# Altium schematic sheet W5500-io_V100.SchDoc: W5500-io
size A4; DrawnBy: Scott; Revision: V100; SheetNumber: 1; SheetTotal: 1; Team: Edge
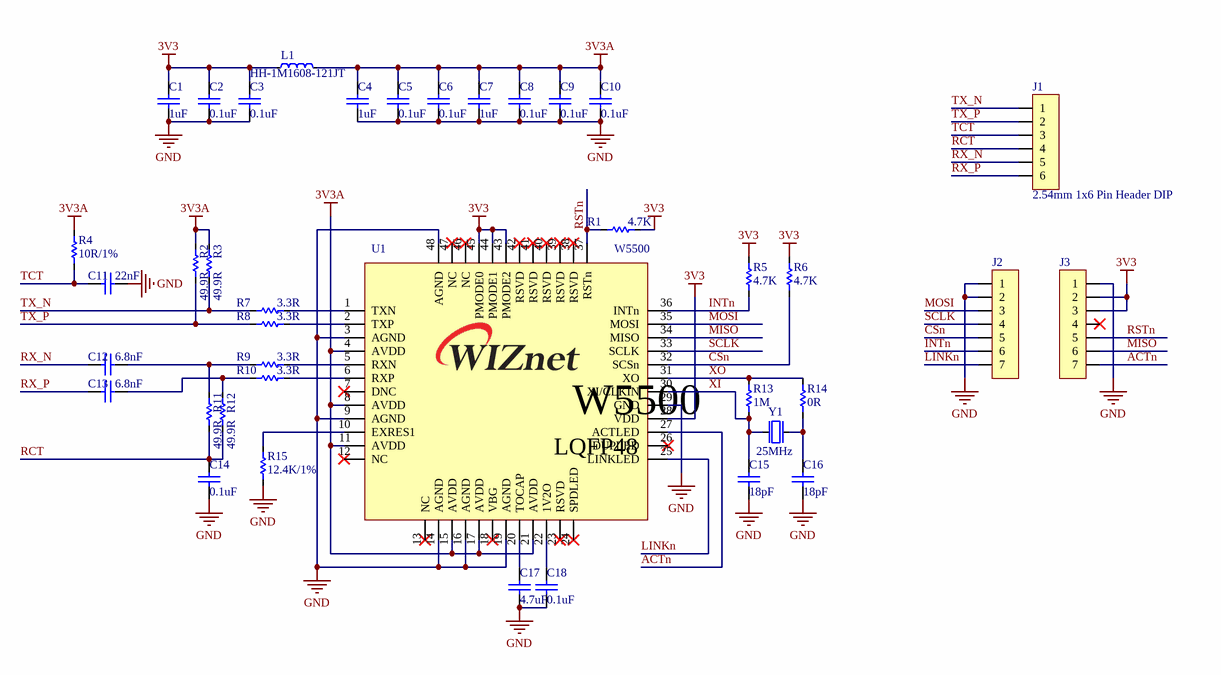
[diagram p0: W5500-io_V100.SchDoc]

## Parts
C1  1uF  [CAP-0402]
C2  0.1uF  [CAP-0402]
C3  0.1uF  [CAP-0402]
C4  1uF  [CAP-0402]
C5  0.1uF  [CAP-0402]
C6  0.1uF  [CAP-0402]
C7  1uF  [CAP-0402]
C8  0.1uF  [CAP-0402]
C9  0.1uF  [CAP-0402]
C10  0.1uF  [CAP-0402]
C11  22nF  [CAP-0402]
C12  6.8nF  [CAP-0402]
C13  6.8nF  [CAP-0402]
C14  0.1uF  [CAP-0402]
C15  18pF  [CAP-0402]
C16  18pF  [CAP-0402]
C17  4.7uF  [CAP-0805]
C18  0.1uF  [CAP-0402]
J1  2.54mm 1x6 Pin Header DIP  [IDC-1X6(WI510IO)]
J2  2.54mm 1x7 Pin Header DIP  [IDC-1X7(WI510IO)]  (value not drawn)
J3  2.54mm 1x7 Pin Header DIP  [IDC-1X7(WI510IO)]  (value not drawn)
L1  HH-1M1608-121JT  [IND-0603]
R1  4.7K  [RES-0402]
R2  49.9R  [RES-0402]
R3  49.9R  [RES-0402]
R4  10R/1%  [RES-0402]
R5  4.7K  [RES-0402]
R6  4.7K  [RES-0402]
R7  3.3R  [RES-0402]
R8  3.3R  [RES-0402]
R9  3.3R  [RES-0402]
R10  3.3R  [RES-0402]
R11  49.9R  [RES-0402]
R12  49.9R  [RES-0402]
R13  1M  [RES-0402]
R14  0R  [RES-0402]
R15  12.4K/1%  [RES-0402]
U1  W5500  [W5500-LQFP48]
Y1  25MHz  [OSC-82J0626]

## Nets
3V3: C1.2 C2.2 C3.2 J3.2 J3.3 L1.1 R1.2 R5.1 R6.1 U1.28(VDD) U1.43(PMODE2) U1.44(PMODE1) U1.45(PMODE0)
3V3A: C4.2 C5.2 C6.2 C7.2 C8.2 C9.2 C10.2 L1.2 R2.2 R3.2 R4.1 U1.4(AVDD) U1.8(AVDD) U1.11(AVDD) U1.15(AVDD) U1.17(AVDD) U1.21(AVDD)
GND: C1.1 C2.1 C3.1 C4.1 C5.1 C6.1 C7.1 C8.1 C9.1 C10.1 C11.1 C14.1 C15.1 C16.1 C17.1 C18.1 J2.1 J2.2 J3.1 R15.2 U1.3(AGND) U1.9(AGND) U1.14(AGND) U1.16(AGND) U1.19(AGND) U1.29(GND) U1.48(AGND) Y1.2(GND) Y1.4(GND)
ACTn: J3.7 U1.27(ACTLED)
CSn: J2.5 R6.2 U1.32(SCSn)
INTn: J2.6 R5.2 U1.36(INTn)
LINKn: J2.7 U1.25(LINKLED)
MISO: J3.6 U1.34(MISO)
MOSI: J2.3 U1.35(MOSI)
RCT: C14.2 J1.4 R11.1 R12.1
RSTn: J3.5 R1.1 U1.37(RSTn)
RX_N: C12.2 J1.5
RX_P: C13.2 J1.6
SCLK: J2.4 U1.33(SCLK)
TCT: C11.2 J1.3 R4.2
TX_N: J1.1 R3.1 R7.1
TX_P: J1.2 R2.1 R8.1
XI: C15.2 R13.1 U1.30(XI/CLKIN) Y1.1(inp)
XO: R13.2 R14.2 U1.31(XO)
NetC12_1: C12.1 R9.1 R11.2
NetC13_1: C13.1 R10.1 R12.2
NetC16_2: C16.2 R14.1 Y1.3(out)
NetC17_2: C17.2 U1.20(TOCAP)
NetC18_2: C18.2 U1.22(1V2O)
NetR7_2: R7.2 U1.1(TXN)
NetR8_2: R8.2 U1.2(TXP)
NetR9_2: R9.2 U1.5(RXN)
NetR10_2: R10.2 U1.6(RXP)
NetR15_1: R15.1 U1.10(EXRES1)

Not connected (* = marked no-connect by the designer): J3 4*; U1 7(DNC)* 12(NC)* 13(NC)* 18(VBG)* 23(RSVD)* 24(SPDLED)* 26(DUPLED)* 38(RSVD)* 39(RSVD)* 40(RSVD)* 41(RSVD)* 42(RSVD)* 46(NC)* 47(NC)*

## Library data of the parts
C1-C16 C18 = CAP-0402: Ceramic CAP 0402(1005)
C17 = CAP-0805: Ceramic CAP 0805(2012)
L1 = IND-0603: Inductor 0603(1608)
R1-R15 = RES-0402
U1 = W5500: WIZnet Hardwired TCP/IP Chip
Y1 = OSC-82J0626-25MHz: X-tal 25MHz,3.2x2.5 SMD, CL=18pF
